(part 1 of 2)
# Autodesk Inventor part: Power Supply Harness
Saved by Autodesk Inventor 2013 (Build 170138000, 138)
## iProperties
Created: 2007-02
Part Number: Power Supply Harness
Document SubType Name: Modeling
Designer: floress
Density: 1 g/cm^3
Material: Allgemein
GlobalPropertyList: <PropertyList/>
Key:2|1|1|0|4|0|0|0|23|0|0|0|Level:1: <CableProperty entityType="Connector" version="1.0"><ID editable="" value=""/><UserDefined><Property name="14121" value="0.125 in" unitCategory="14110" custom="
Key:2|1|1|0|4|0|0|0|54|0|0|0|Level:1: <CableProperty entityType="Connector" version="1.0"><ID editable="" value=""/><UserDefined><Property name="14121" value="0.125 in" unitCategory="14110" custom="
Key:2|1|1|0|4|0|0|0|20|0|0|0|Level:1: <CableProperty entityType="Connector" version="1.0"><ID editable="" value=""/><UserDefined><Property name="14121" value="0.125 in" unitCategory="14110" custom="
Key:2|1|1|0|4|0|0|0|19|0|0|0|Level:1: <CableProperty entityType="Connector" version="1.0"><ID editable="" value=""/><UserDefined><Property name="14121" value="0.125 in" unitCategory="14110" custom="
Key:2|1|1|0|4|0|0|0|18|0|0|0|Level:1: <CableProperty entityType="Connector" version="1.0"><ID editable="" value=""/><UserDefined><Property name="14121" value="0.125 in" unitCategory="14110" custom="
Key:2|1|1|0|4|0|0|0|21|0|0|0|Level:1: <CableProperty entityType="Connector" version="1.0"><ID editable="" value=""/><UserDefined><Property name="14121" value="0.125 in" unitCategory="14110" custom="
Key:2|1|1|0|4|0|0|0|22|0|0|0|Level:1: <CableProperty entityType="Connector" version="1.0"><ID editable="" value=""/><UserDefined><Property name="14121" value="0.125 in" unitCategory="14110" custom="
Key:2|1|1|0|4|0|0|0|24|0|0|0|Level:1: <CableProperty entityType="Connector" version="1.0"><ID editable="" value=""/><UserDefined><Property name="14121" value="0.125 in" unitCategory="14110" custom="
Key:2|1|1|0|4|0|0|0|25|0|0|0|Level:1: <CableProperty entityType="Connector" version="1.0"><ID editable="" value=""/><UserDefined><Property name="14121" value="0.125 in" unitCategory="14110" custom="
Key:2|1|1|0|4|0|0|0|26|0|0|0|Level:1: <CableProperty entityType="Connector" version="1.0"><ID editable="" value=""/><UserDefined><Property name="14121" value="0.125 in" unitCategory="14110" custom="
Key:2|1|1|0|4|0|0|0|27|0|0|0|Level:1: <CableProperty entityType="Connector" version="1.0"><ID editable="" value=""/><UserDefined><Property name="14121" value="0.125 in" unitCategory="14110" custom="
Key:2|1|1|0|4|0|0|0|28|0|0|0|Level:1: <CableProperty entityType="Connector" version="1.0"><ID editable="" value=""/><UserDefined><Property name="14121" value="0.125 in" unitCategory="14110" custom="
Key:2|1|1|0|4|0|0|0|29|0|0|0|Level:1: <CableProperty entityType="Connector" version="1.0"><ID editable="" value=""/><UserDefined><Property name="14121" value="0.125 in" unitCategory="14110" custom="
Key:2|1|1|0|4|0|0|0|30|0|0|0|Level:1: <CableProperty entityType="Connector" version="1.0"><ID editable="" value=""/><UserDefined><Property name="14121" value="0.125 in" unitCategory="14110" custom="
Key:2|1|1|0|4|0|0|0|31|0|0|0|Level:1: <CableProperty entityType="Connector" version="1.0"><ID editable="" value=""/><UserDefined><Property name="14121" value="0.125 in" unitCategory="14110" custom="
Key:2|1|1|0|4|0|0|0|32|0|0|0|Level:1: <CableProperty entityType="Connector" version="1.0"><ID editable="" value=""/><UserDefined><Property name="14121" value="0.125 in" unitCategory="14110" custom="
Key:2|1|1|0|4|0|0|0|33|0|0|0|Level:1: <CableProperty entityType="Connector" version="1.0"><ID editable="" value=""/><UserDefined><Property name="14121" value="0.125 in" unitCategory="14110" custom="
Key:2|1|1|0|4|0|0|0|34|0|0|0|Level:1: <CableProperty entityType="Connector" version="1.0"><ID editable="" value=""/><UserDefined><Property name="14121" value="0.125 in" unitCategory="14110" custom="
Key:2|1|1|0|4|0|0|0|35|0|0|0|Level:1: <CableProperty entityType="Connector" version="1.0"><ID editable="" value=""/><UserDefined><Property name="14121" value="0.125 in" unitCategory="14110" custom="
Key:2|1|1|0|4|0|0|0|36|0|0|0|Level:1: <CableProperty entityType="Connector" version="1.0"><ID editable="" value=""/><UserDefined><Property name="14121" value="0.125 in" unitCategory="14110" custom="
Key:2|1|1|0|4|0|0|0|37|0|0|0|Level:1: <CableProperty entityType="Connector" version="1.0"><ID editable="" value=""/><UserDefined><Property name="14121" value="0.125 in" unitCategory="14110" custom="
Key:2|1|1|0|4|0|0|0|38|0|0|0|Level:1: <CableProperty entityType="Connector" version="1.0"><ID editable="" value=""/><UserDefined><Property name="14121" value="0.125 in" unitCategory="14110" custom="
Key:2|1|1|0|4|0|0|0|39|0|0|0|Level:1: <CableProperty entityType="Connector" version="1.0"><ID editable="" value=""/><UserDefined><Property name="14121" value="0.125 in" unitCategory="14110" custom="
Key:2|1|1|0|4|0|0|0|40|0|0|0|Level:1: <CableProperty entityType="Connector" version="1.0"><ID editable="" value=""/><UserDefined><Property name="14121" value="0.125 in" unitCategory="14110" custom="
Key:2|1|1|0|4|0|0|0|41|0|0|0|Level:1: <CableProperty entityType="Connector" version="1.0"><ID editable="" value=""/><UserDefined><Property name="14121" value="0.125 in" unitCategory="14110" custom="
Key:2|1|1|0|4|0|0|0|42|0|0|0|Level:1: <CableProperty entityType="Connector" version="1.0"><ID editable="" value=""/><UserDefined><Property name="14121" value="0.125 in" unitCategory="14110" custom="
Key:2|1|1|0|4|0|0|0|43|0|0|0|Level:1: <CableProperty entityType="Connector" version="1.0"><ID editable="" value=""/><UserDefined><Property name="14121" value="0.125 in" unitCategory="14110" custom="
Key:2|1|1|0|4|0|0|0|44|0|0|0|Level:1: <CableProperty entityType="Connector" version="1.0"><ID editable="" value=""/><UserDefined><Property name="14121" value="0.125 in" unitCategory="14110" custom="
Key:2|1|1|0|4|0|0|0|45|0|0|0|Level:1: <CableProperty entityType="Connector" version="1.0"><ID editable="" value=""/><UserDefined><Property name="14121" value="0.125 in" unitCategory="14110" custom="
Key:2|1|1|0|4|0|0|0|46|0|0|0|Level:1: <CableProperty entityType="Connector" version="1.0"><ID editable="" value=""/><UserDefined><Property name="14121" value="0.125 in" unitCategory="14110" custom="
Key:2|1|1|0|4|0|0|0|47|0|0|0|Level:1: <CableProperty entityType="Connector" version="1.0"><ID editable="" value=""/><UserDefined><Property name="14121" value="0.125 in" unitCategory="14110" custom="
Key:2|1|1|0|4|0|0|0|48|0|0|0|Level:1: <CableProperty entityType="Connector" version="1.0"><ID editable="" value=""/><UserDefined><Property name="14121" value="0.125 in" unitCategory="14110" custom="
Key:2|1|1|0|4|0|0|0|49|0|0|0|Level:1: <CableProperty entityType="Connector" version="1.0"><ID editable="" value=""/><UserDefined><Property name="14121" value="0.125 in" unitCategory="14110" custom="
Key:2|1|1|0|4|0|0|0|50|0|0|0|Level:1: <CableProperty entityType="Connector" version="1.0"><ID editable="" value=""/><UserDefined><Property name="14121" value="0.125 in" unitCategory="14110" custom="
Key:2|1|1|0|4|0|0|0|51|0|0|0|Level:1: <CableProperty entityType="Connector" version="1.0"><ID editable="" value=""/><UserDefined><Property name="14121" value="0.125 in" unitCategory="14110" custom="
Key:2|1|1|0|4|0|0|0|52|0|0|0|Level:1: <CableProperty entityType="Connector" version="1.0"><ID editable="" value=""/><UserDefined><Property name="14121" value="0.125 in" unitCategory="14110" custom="
Key:2|1|1|0|4|0|0|0|53|0|0|0|Level:1: <CableProperty entityType="Connector" version="1.0"><ID editable="" value=""/><UserDefined><Property name="14121" value="0.125 in" unitCategory="14110" custom="
Key:2|1|1|0|4|0|0|0|55|0|0|0|Level:1: <CableProperty entityType="Connector" version="1.0"><ID editable="" value=""/><UserDefined><Property name="14121" value="0.125 in" unitCategory="14110" custom="
Key:2|1|1|0|4|0|0|0|56|0|0|0|Level:1: <CableProperty entityType="Connector" version="1.0"><ID editable="" value=""/><UserDefined><Property name="14121" value="0.125 in" unitCategory="14110" custom="
Key:2|1|2|0|36|0|0|0|2|1|1|0|4|0|0|0|23|0|0|0|16|2|0|0|16|0|: <CableProperty entityType="ConnectorPin" version="1.0"><ID editable="" value=""/><UserDefined/><PinName editable="True" value="1"/><AttachedParts><AttachedPart 
Key:2|1|2|0|36|0|0|0|2|1|1|0|4|0|0|0|23|0|0|0|16|2|0|0|16|0|: <CableProperty entityType="ConnectorPin" version="1.0"><ID editable="" value=""/><UserDefined/><PinName editable="True" value="2"/><AttachedParts><AttachedPart 
Key:2|1|2|0|36|0|0|0|2|1|1|0|4|0|0|0|23|0|0|0|16|2|0|0|16|0|: <CableProperty entityType="ConnectorPin" version="1.0"><ID editable="" value=""/><UserDefined/><PinName editable="True" value="3"/><AttachedParts><AttachedPart 
Key:2|1|2|0|36|0|0|0|2|1|1|0|4|0|0|0|23|0|0|0|16|2|0|0|16|0|: <CableProperty entityType="ConnectorPin" version="1.0"><ID editable="" value=""/><UserDefined/><PinName editable="True" value="4"/><AttachedParts><AttachedPart 
Key:2|1|2|0|36|0|0|0|2|1|1|0|4|0|0|0|23|0|0|0|16|2|0|0|16|0|: <CableProperty entityType="ConnectorPin" version="1.0"><ID editable="" value=""/><UserDefined/><PinName editable="True" value="5"/><AttachedParts><AttachedPart 
Key:2|1|2|0|36|0|0|0|2|1|1|0|4|0|0|0|23|0|0|0|16|2|0|0|16|0|: <CableProperty entityType="ConnectorPin" version="1.0"><ID editable="" value=""/><UserDefined/><PinName editable="True" value="6"/><AttachedParts><AttachedPart 
Key:2|1|2|0|36|0|0|0|2|1|1|0|4|0|0|0|23|0|0|0|16|2|0|0|16|0|: <CableProperty entityType="ConnectorPin" version="1.0"><ID editable="" value=""/><UserDefined/><PinName editable="True" value="7"/><AttachedParts><AttachedPart 
Key:2|1|2|0|36|0|0|0|2|1|1|0|4|0|0|0|23|0|0|0|16|2|0|0|16|0|: <CableProperty entityType="ConnectorPin" version="1.0"><ID editable="" value=""/><UserDefined/><PinName editable="True" value="8"/><AttachedParts><AttachedPart 
Key:2|1|2|0|36|0|0|0|2|1|1|0|4|0|0|0|23|0|0|0|16|2|0|0|16|0|: <CableProperty entityType="ConnectorPin" version="1.0"><ID editable="" value=""/><UserDefined/><PinName editable="True" value="9"/><AttachedParts><AttachedPart 
Key:2|1|2|0|36|0|0|0|2|1|1|0|4|0|0|0|23|0|0|0|16|2|0|0|16|0|: <CableProperty entityType="ConnectorPin" version="1.0"><ID editable="" value=""/><UserDefined/><PinName editable="True" value="10"/><AttachedParts><AttachedPart
Key:2|1|2|0|36|0|0|0|2|1|1|0|4|0|0|0|23|0|0|0|16|2|0|0|16|0|: <CableProperty entityType="ConnectorPin" version="1.0"><ID editable="" value=""/><UserDefined/><PinName editable="True" value="11"/><AttachedParts><AttachedPart
Key:2|1|2|0|36|0|0|0|2|1|1|0|4|0|0|0|23|0|0|0|16|2|0|0|16|0|: <CableProperty entityType="ConnectorPin" version="1.0"><ID editable="" value=""/><UserDefined/><PinName editable="True" value="12"/><AttachedParts><AttachedPart
Key:2|1|2|0|36|0|0|0|2|1|1|0|4|0|0|0|23|0|0|0|16|2|0|0|16|0|: <CableProperty entityType="ConnectorPin" version="1.0"><ID editable="" value=""/><UserDefined/><PinName editable="True" value="13"/><AttachedParts><AttachedPart
Key:2|1|2|0|36|0|0|0|2|1|1|0|4|0|0|0|23|0|0|0|16|2|0|0|16|0|: <CableProperty entityType="ConnectorPin" version="1.0"><ID editable="" value=""/><UserDefined/><PinName editable="True" value="14"/><AttachedParts><AttachedPart
Key:2|1|2|0|36|0|0|0|2|1|1|0|4|0|0|0|23|0|0|0|16|2|0|0|16|0|: <CableProperty entityType="ConnectorPin" version="1.0"><ID editable="" value=""/><UserDefined/><PinName editable="True" value="15"/><AttachedParts><AttachedPart
Key:2|1|2|0|36|0|0|0|2|1|1|0|4|0|0|0|23|0|0|0|16|2|0|0|16|0|: <CableProperty entityType="ConnectorPin" version="1.0"><ID editable="" value=""/><UserDefined/><PinName editable="True" value="16"/><AttachedParts><AttachedPart
Key:2|1|2|0|36|0|0|0|2|1|1|0|4|0|0|0|23|0|0|0|16|2|0|0|16|0|: <CableProperty entityType="ConnectorPin" version="1.0"><ID editable="" value=""/><UserDefined/><PinName editable="True" value="17"/><AttachedParts><AttachedPart
Key:2|1|2|0|36|0|0|0|2|1|1|0|4|0|0|0|23|0|0|0|16|2|0|0|16|0|: <CableProperty entityType="ConnectorPin" version="1.0"><ID editable="" value=""/><UserDefined/><PinName editable="True" value="18"/><AttachedParts><AttachedPart
Key:2|1|2|0|36|0|0|0|2|1|1|0|4|0|0|0|23|0|0|0|16|2|0|0|16|0|: <CableProperty entityType="ConnectorPin" version="1.0"><ID editable="" value=""/><UserDefined/><PinName editable="True" value="19"/><AttachedParts><AttachedPart
Key:2|1|2|0|36|0|0|0|2|1|1|0|4|0|0|0|23|0|0|0|16|2|0|0|16|0|: <CableProperty entityType="ConnectorPin" version="1.0"><ID editable="" value=""/><UserDefined/><PinName editable="True" value="20"/><AttachedParts><AttachedPart
Key:2|1|2|0|36|0|0|0|2|1|1|0|4|0|0|0|19|0|0|0|16|2|0|0|16|0|: <CableProperty entityType="ConnectorPin" version="1.0"><ID editable="" value=""/><UserDefined/><PinName editable="True" value="1"/><AttachedParts><AttachedPart 
Key:2|1|2|0|36|0|0|0|2|1|1|0|4|0|0|0|19|0|0|0|16|2|0|0|16|0|: <CableProperty entityType="ConnectorPin" version="1.0"><ID editable="" value=""/><UserDefined/><PinName editable="True" value="2"/><AttachedParts><AttachedPart 
Key:2|1|2|0|36|0|0|0|2|1|1|0|4|0|0|0|19|0|0|0|16|2|0|0|16|0|: <CableProperty entityType="ConnectorPin" version="1.0"><ID editable="" value=""/><UserDefined/><PinName editable="True" value="3"/><AttachedParts><AttachedPart 
Key:2|1|2|0|36|0|0|0|2|1|1|0|4|0|0|0|19|0|0|0|16|2|0|0|16|0|: <CableProperty entityType="ConnectorPin" version="1.0"><ID editable="" value=""/><UserDefined/><PinName editable="True" value="4"/><AttachedParts><AttachedPart 
Key:2|1|2|0|36|0|0|0|2|1|1|0|4|0|0|0|20|0|0|0|16|2|0|0|16|0|: <CableProperty entityType="ConnectorPin" version="1.0"><ID editable="" value=""/><UserDefined/><PinName editable="True" value="1"/><AttachedParts><AttachedPart 
Key:2|1|2|0|36|0|0|0|2|1|1|0|4|0|0|0|20|0|0|0|16|2|0|0|16|0|: <CableProperty entityType="ConnectorPin" version="1.0"><ID editable="" value=""/><UserDefined/><PinName editable="True" value="2"/><AttachedParts><AttachedPart 
Key:2|1|2|0|36|0|0|0|2|1|1|0|4|0|0|0|20|0|0|0|16|2|0|0|16|0|: <CableProperty entityType="ConnectorPin" version="1.0"><ID editable="" value=""/><UserDefined/><PinName editable="True" value="3"/><AttachedParts><AttachedPart 
Key:2|1|2|0|36|0|0|0|2|1|1|0|4|0|0|0|20|0|0|0|16|2|0|0|16|0|: <CableProperty entityType="ConnectorPin" version="1.0"><ID editable="" value=""/><UserDefined/><PinName editable="True" value="4"/><AttachedParts><AttachedPart 
Key:2|1|2|0|36|0|0|0|2|1|1|0|4|0|0|0|54|0|0|0|16|2|0|0|16|0|: <CableProperty entityType="ConnectorPin" version="1.0"><ID editable="" value=""/><UserDefined/><PinName editable="True" value="1"/><AttachedParts><AttachedPart 
Key:2|1|2|0|36|0|0|0|2|1|1|0|4|0|0|0|54|0|0|0|16|2|0|0|16|0|: <CableProperty entityType="ConnectorPin" version="1.0"><ID editable="" value=""/><UserDefined/><PinName editable="True" value="2"/><AttachedParts><AttachedPart 
Key:2|1|2|0|36|0|0|0|2|1|1|0|4|0|0|0|54|0|0|0|16|2|0|0|16|0|: <CableProperty entityType="ConnectorPin" version="1.0"><ID editable="" value=""/><UserDefined/><PinName editable="True" value="3"/><AttachedParts><AttachedPart 
Key:2|1|2|0|36|0|0|0|2|1|1|0|4|0|0|0|54|0|0|0|16|2|0|0|16|0|: <CableProperty entityType="ConnectorPin" version="1.0"><ID editable="" value=""/><UserDefined/><PinName editable="True" value="4"/><AttachedParts><AttachedPart 
Key:2|1|2|0|36|0|0|0|2|1|1|0|4|0|0|0|18|0|0|0|16|2|0|0|16|0|: <CableProperty entityType="ConnectorPin" version="1.0"><ID editable="" value=""/><UserDefined/><PinName editable="True" value="1"/><AttachedParts><AttachedPart 
Key:2|1|2|0|36|0|0|0|2|1|1|0|4|0|0|0|18|0|0|0|16|2|0|0|16|0|: <CableProperty entityType="ConnectorPin" version="1.0"><ID editable="" value=""/><UserDefined/><PinName editable="True" value="2"/><AttachedParts><AttachedPart 
Key:2|1|2|0|36|0|0|0|2|1|1|0|4|0|0|0|18|0|0|0|16|2|0|0|16|0|: <CableProperty entityType="ConnectorPin" version="1.0"><ID editable="" value=""/><UserDefined/><PinName editable="True" value="3"/><AttachedParts><AttachedPart 
Key:2|1|2|0|36|0|0|0|2|1|1|0|4|0|0|0|18|0|0|0|16|2|0|0|16|0|: <CableProperty entityType="ConnectorPin" version="1.0"><ID editable="" value=""/><UserDefined/><PinName editable="True" value="4"/><AttachedParts><AttachedPart 
Key:2|1|2|0|36|0|0|0|2|1|1|0|4|0|0|0|21|0|0|0|16|2|0|0|16|0|: <CableProperty entityType="ConnectorPin" version="1.0"><ID editable="" value=""/><UserDefined/><PinName editable="True" value="1"/><AttachedParts><AttachedPart 
Key:2|1|2|0|36|0|0|0|2|1|1|0|4|0|0|0|21|0|0|0|16|2|0|0|16|0|: <CableProperty entityType="ConnectorPin" version="1.0"><ID editable="" value=""/><UserDefined/><PinName editable="True" value="2"/><AttachedParts><AttachedPart 
Key:2|1|2|0|36|0|0|0|2|1|1|0|4|0|0|0|21|0|0|0|16|2|0|0|16|0|: <CableProperty entityType="ConnectorPin" version="1.0"><ID editable="" value=""/><UserDefined/><PinName editable="True" value="3"/><AttachedParts><AttachedPart 
Key:2|1|2|0|36|0|0|0|2|1|1|0|4|0|0|0|21|0|0|0|16|2|0|0|16|0|: <CableProperty entityType="ConnectorPin" version="1.0"><ID editable="" value=""/><UserDefined/><PinName editable="True" value="4"/><AttachedParts><AttachedPart 
Key:2|1|2|0|36|0|0|0|2|1|1|0|4|0|0|0|22|0|0|0|16|2|0|0|16|0|: <CableProperty entityType="ConnectorPin" version="1.0"><ID editable="" value=""/><UserDefined/><PinName editable="True" value="1"/><AttachedParts><AttachedPart 
Key:2|1|2|0|36|0|0|0|2|1|1|0|4|0|0|0|22|0|0|0|16|2|0|0|16|0|: <CableProperty entityType="ConnectorPin" version="1.0"><ID editable="" value=""/><UserDefined/><PinName editable="True" value="2"/><AttachedParts><AttachedPart 
Key:2|1|2|0|36|0|0|0|2|1|1|0|4|0|0|0|22|0|0|0|16|2|0|0|16|0|: <CableProperty entityType="ConnectorPin" version="1.0"><ID editable="" value=""/><UserDefined/><PinName editable="True" value="3"/><AttachedParts><AttachedPart 
Key:2|1|2|0|36|0|0|0|2|1|1|0|4|0|0|0|22|0|0|0|16|2|0|0|16|0|: <CableProperty entityType="ConnectorPin" version="1.0"><ID editable="" value=""/><UserDefined/><PinName editable="True" value="4"/><AttachedParts><AttachedPart 
Key:2|1|1|0|4|0|0|0|166|0|0|0|Level:1: <CableProperty entityType="Connector" version="1.0"><ID editable="" value=""/><UserDefined><Property name="14121" value="0.125 in" unitCategory="14110" custom="
Key:2|1|1|0|4|0|0|0|167|0|0|0|Level:1: <CableProperty entityType="Connector" version="1.0"><ID editable="" value=""/><UserDefined><Property name="14121" value="0.125 in" unitCategory="14110" custom="
Key:2|1|1|0|4|0|0|0|168|0|0|0|Level:1: <CableProperty entityType="Connector" version="1.0"><ID editable="" value=""/><UserDefined><Property name="14121" value="0.125 in" unitCategory="14110" custom="
Key:2|1|1|0|4|0|0|0|169|0|0|0|Level:1: <CableProperty entityType="Connector" version="1.0"><ID editable="" value=""/><UserDefined><Property name="14121" value="0.125 in" unitCategory="14110" custom="
Key:2|1|1|0|4|0|0|0|170|0|0|0|Level:1: <CableProperty entityType="Connector" version="1.0"><ID editable="" value=""/><UserDefined><Property name="14121" value="0.125 in" unitCategory="14110" custom="
Key:2|1|1|0|4|0|0|0|171|0|0|0|Level:1: <CableProperty entityType="Connector" version="1.0"><ID editable="" value=""/><UserDefined><Property name="14121" value="0.125 in" unitCategory="14110" custom="
Key:2|1|1|0|4|0|0|0|172|0|0|0|Level:1: <CableProperty entityType="Connector" version="1.0"><ID editable="" value=""/><UserDefined><Property name="14121" value="0.125 in" unitCategory="14110" custom="
Key:2|1|1|0|4|0|0|0|173|0|0|0|Level:1: <CableProperty entityType="Connector" version="1.0"><ID editable="" value=""/><UserDefined><Property name="14121" value="0.125 in" unitCategory="14110" custom="
Key:2|1|1|0|4|0|0|0|174|0|0|0|Level:1: <CableProperty entityType="Connector" version="1.0"><ID editable="" value=""/><UserDefined><Property name="14121" value="0.125 in" unitCategory="14110" custom="
Key:2|1|1|0|4|0|0|0|175|0|0|0|Level:1: <CableProperty entityType="Connector" version="1.0"><ID editable="" value=""/><UserDefined><Property name="14121" value="0.125 in" unitCategory="14110" custom="
Key:2|1|1|0|4|0|0|0|176|0|0|0|Level:1: <CableProperty entityType="Connector" version="1.0"><ID editable="" value=""/><UserDefined><Property name="14121" value="0.125 in" unitCategory="14110" custom="
Key:2|1|1|0|4|0|0|0|177|0|0|0|Level:1: <CableProperty entityType="Connector" version="1.0"><ID editable="" value=""/><UserDefined><Property name="14121" value="0.125 in" unitCategory="14110" custom="
Key:2|1|1|0|4|0|0|0|178|0|0|0|Level:1: <CableProperty entityType="Connector" version="1.0"><ID editable="" value=""/><UserDefined><Property name="14121" value="0.125 in" unitCategory="14110" custom="
Key:2|1|1|0|4|0|0|0|179|0|0|0|Level:1: <CableProperty entityType="Connector" version="1.0"><ID editable="" value=""/><UserDefined><Property name="14121" value="0.125 in" unitCategory="14110" custom="
Key:2|1|1|0|4|0|0|0|180|0|0|0|Level:1: <CableProperty entityType="Connector" version="1.0"><ID editable="" value=""/><UserDefined><Property name="14121" value="0.125 in" unitCategory="14110" custom="
Key:2|1|1|0|4|0|0|0|181|0|0|0|Level:1: <CableProperty entityType="Connector" version="1.0"><ID editable="" value=""/><UserDefined><Property name="14121" value="0.125 in" unitCategory="14110" custom="
Key:2|1|1|0|4|0|0|0|182|0|0|0|Level:1: <CableProperty entityType="Connector" version="1.0"><ID editable="" value=""/><UserDefined><Property name="14121" value="0.125 in" unitCategory="14110" custom="
Key:2|1|1|0|4|0|0|0|183|0|0|0|Level:1: <CableProperty entityType="Connector" version="1.0"><ID editable="" value=""/><UserDefined><Property name="14121" value="0.125 in" unitCategory="14110" custom="
Key:2|1|1|0|4|0|0|0|184|0|0|0|Level:1: <CableProperty entityType="Connector" version="1.0"><ID editable="" value=""/><UserDefined><Property name="14121" value="0.125 in" unitCategory="14110" custom="
Key:2|1|1|0|4|0|0|0|185|0|0|0|Level:1: <CableProperty entityType="Connector" version="1.0"><ID editable="" value=""/><UserDefined><Property name="14121" value="0.125 in" unitCategory="14110" custom="
Key:2|1|1|0|4|0|0|0|186|0|0|0|Level:1: <CableProperty entityType="Connector" version="1.0"><ID editable="" value=""/><UserDefined><Property name="14121" value="0.125 in" unitCategory="14110" custom="
Key:2|1|1|0|4|0|0|0|187|0|0|0|Level:1: <CableProperty entityType="Connector" version="1.0"><ID editable="" value=""/><UserDefined><Property name="14121" value="0.125 in" unitCategory="14110" custom="
Key:2|1|1|0|4|0|0|0|158|0|0|0|Level:1: <CableProperty entityType="Connector" version="1.0"><ID editable="" value=""/><UserDefined><Property name="14121" value="0.125 in" unitCategory="14110" custom="
Key:2|1|1|0|4|0|0|0|159|0|0|0|Level:1: <CableProperty entityType="Connector" version="1.0"><ID editable="" value=""/><UserDefined><Property name="14121" value="0.125 in" unitCategory="14110" custom="
Key:2|1|1|0|4|0|0|0|160|0|0|0|Level:1: <CableProperty entityType="Connector" version="1.0"><ID editable="" value=""/><UserDefined><Property name="14121" value="0.125 in" unitCategory="14110" custom="
Key:2|1|1|0|4|0|0|0|161|0|0|0|Level:1: <CableProperty entityType="Connector" version="1.0"><ID editable="" value=""/><UserDefined><Property name="14121" value="0.125 in" unitCategory="14110" custom="
Key:2|1|1|0|4|0|0|0|162|0|0|0|Level:1: <CableProperty entityType="Connector" version="1.0"><ID editable="" value=""/><UserDefined><Property name="14121" value="0.125 in" unitCategory="14110" custom="
Key:2|1|1|0|4|0|0|0|163|0|0|0|Level:1: <CableProperty entityType="Connector" version="1.0"><ID editable="" value=""/><UserDefined><Property name="14121" value="0.125 in" unitCategory="14110" custom="
Key:2|1|1|0|4|0|0|0|164|0|0|0|Level:1: <CableProperty entityType="Connector" version="1.0"><ID editable="" value=""/><UserDefined><Property name="14121" value="0.125 in" unitCategory="14110" custom="
Key:2|1|1|0|4|0|0|0|165|0|0|0|Level:1: <CableProperty entityType="Connector" version="1.0"><ID editable="" value=""/><UserDefined><Property name="14121" value="0.125 in" unitCategory="14110" custom="
Key:2|1|1|0|4|0|0|0|157|0|0|0|Level:1: <CableProperty entityType="Connector" version="1.0"><ID editable="" value=""/><UserDefined><Property name="14121" value="0.125 in" unitCategory="14110" custom="
Key:2|1|1|0|4|0|0|0|153|0|0|0|Level:1: <CableProperty entityType="Connector" version="1.0"><ID editable="" value=""/><UserDefined><Property name="14121" value="0.125 in" unitCategory="14110" custom="
Key:2|1|1|0|4|0|0|0|154|0|0|0|Level:1: <CableProperty entityType="Connector" version="1.0"><ID editable="" value=""/><UserDefined><Property name="14121" value="0.125 in" unitCategory="14110" custom="
Key:2|1|1|0|4|0|0|0|188|0|0|0|Level:1: <CableProperty entityType="Connector" version="1.0"><ID editable="" value=""/><UserDefined><Property name="14121" value="0.125 in" unitCategory="14110" custom="
Key:2|1|1|0|4|0|0|0|152|0|0|0|Level:1: <CableProperty entityType="Connector" version="1.0"><ID editable="" value=""/><UserDefined><Property name="14121" value="0.125 in" unitCategory="14110" custom="
Key:2|1|1|0|4|0|0|0|155|0|0|0|Level:1: <CableProperty entityType="Connector" version="1.0"><ID editable="" value=""/><UserDefined><Property name="14121" value="0.125 in" unitCategory="14110" custom="
Key:2|1|1|0|4|0|0|0|156|0|0|0|Level:1: <CableProperty entityType="Connector" version="1.0"><ID editable="" value=""/><UserDefined><Property name="14121" value="0.125 in" unitCategory="14110" custom="
Key:2|1|1|0|4|0|0|0|189|0|0|0|Level:1: <CableProperty entityType="Connector" version="1.0"><ID editable="" value=""/><UserDefined><Property name="14121" value="0.125 in" unitCategory="14110" custom="
Key:2|1|1|0|4|0|0|0|190|0|0|0|Level:1: <CableProperty entityType="Connector" version="1.0"><ID editable="" value=""/><UserDefined><Property name="14121" value="0.125 in" unitCategory="14110" custom="
Key:2|1|2|0|36|0|0|0|2|1|1|0|4|0|0|0|157|0|0|0|16|2|0|0|16|0: <CableProperty entityType="ConnectorPin" version="1.0"><ID editable="" value=""/><UserDefined/><PinName editable="True" value="1"/><AttachedParts><AttachedPart 
Key:2|1|2|0|36|0|0|0|2|1|1|0|4|0|0|0|157|0|0|0|16|2|0|0|16|0: <CableProperty entityType="ConnectorPin" version="1.0"><ID editable="" value=""/><UserDefined/><PinName editable="True" value="2"/><AttachedParts><AttachedPart 
Key:2|1|2|0|36|0|0|0|2|1|1|0|4|0|0|0|157|0|0|0|16|2|0|0|16|0: <CableProperty entityType="ConnectorPin" version="1.0"><ID editable="" value=""/><UserDefined/><PinName editable="True" value="3"/><AttachedParts><AttachedPart 
Key:2|1|2|0|36|0|0|0|2|1|1|0|4|0|0|0|157|0|0|0|16|2|0|0|16|0: <CableProperty entityType="ConnectorPin" version="1.0"><ID editable="" value=""/><UserDefined/><PinName editable="True" value="4"/><AttachedParts><AttachedPart 
Key:2|1|2|0|36|0|0|0|2|1|1|0|4|0|0|0|157|0|0|0|16|2|0|0|16|0: <CableProperty entityType="ConnectorPin" version="1.0"><ID editable="" value=""/><UserDefined/><PinName editable="True" value="5"/><AttachedParts><AttachedPart 
Key:2|1|2|0|36|0|0|0|2|1|1|0|4|0|0|0|157|0|0|0|16|2|0|0|16|0: <CableProperty entityType="ConnectorPin" version="1.0"><ID editable="" value=""/><UserDefined/><PinName editable="True" value="6"/><AttachedParts><AttachedPart 
Key:2|1|2|0|36|0|0|0|2|1|1|0|4|0|0|0|157|0|0|0|16|2|0|0|16|0: <CableProperty entityType="ConnectorPin" version="1.0"><ID editable="" value=""/><UserDefined/><PinName editable="True" value="7"/><AttachedParts><AttachedPart 
Key:2|1|2|0|36|0|0|0|2|1|1|0|4|0|0|0|157|0|0|0|16|2|0|0|16|0: <CableProperty entityType="ConnectorPin" version="1.0"><ID editable="" value=""/><UserDefined/><PinName editable="True" value="8"/><AttachedParts><AttachedPart 
Key:2|1|2|0|36|0|0|0|2|1|1|0|4|0|0|0|157|0|0|0|16|2|0|0|16|0: <CableProperty entityType="ConnectorPin" version="1.0"><ID editable="" value=""/><UserDefined/><PinName editable="True" value="9"/><AttachedParts><AttachedPart 
Key:2|1|2|0|36|0|0|0|2|1|1|0|4|0|0|0|157|0|0|0|16|2|0|0|16|0: <CableProperty entityType="ConnectorPin" version="1.0"><ID editable="" value=""/><UserDefined/><PinName editable="True" value="10"/><AttachedParts><AttachedPart
Key:2|1|2|0|36|0|0|0|2|1|1|0|4|0|0|0|157|0|0|0|16|2|0|0|16|0: <CableProperty entityType="ConnectorPin" version="1.0"><ID editable="" value=""/><UserDefined/><PinName editable="True" value="11"/><AttachedParts><AttachedPart
Key:2|1|2|0|36|0|0|0|2|1|1|0|4|0|0|0|157|0|0|0|16|2|0|0|16|0: <CableProperty entityType="ConnectorPin" version="1.0"><ID editable="" value=""/><UserDefined/><PinName editable="True" value="12"/><AttachedParts><AttachedPart
Key:2|1|2|0|36|0|0|0|2|1|1|0|4|0|0|0|157|0|0|0|16|2|0|0|16|0: <CableProperty entityType="ConnectorPin" version="1.0"><ID editable="" value=""/><UserDefined/><PinName editable="True" value="13"/><AttachedParts><AttachedPart
Key:2|1|2|0|36|0|0|0|2|1|1|0|4|0|0|0|157|0|0|0|16|2|0|0|16|0: <CableProperty entityType="ConnectorPin" version="1.0"><ID editable="" value=""/><UserDefined/><PinName editable="True" value="14"/><AttachedParts><AttachedPart
Key:2|1|2|0|36|0|0|0|2|1|1|0|4|0|0|0|157|0|0|0|16|2|0|0|16|0: <CableProperty entityType="ConnectorPin" version="1.0"><ID editable="" value=""/><UserDefined/><PinName editable="True" value="15"/><AttachedParts><AttachedPart
Key:2|1|2|0|36|0|0|0|2|1|1|0|4|0|0|0|157|0|0|0|16|2|0|0|16|0: <CableProperty entityType="ConnectorPin" version="1.0"><ID editable="" value=""/><UserDefined/><PinName editable="True" value="16"/><AttachedParts><AttachedPart
Key:2|1|2|0|36|0|0|0|2|1|1|0|4|0|0|0|157|0|0|0|16|2|0|0|16|0: <CableProperty entityType="ConnectorPin" version="1.0"><ID editable="" value=""/><UserDefined/><PinName editable="True" value="17"/><AttachedParts><AttachedPart
Key:2|1|2|0|36|0|0|0|2|1|1|0|4|0|0|0|157|0|0|0|16|2|0|0|16|0: <CableProperty entityType="ConnectorPin" version="1.0"><ID editable="" value=""/><UserDefined/><PinName editable="True" value="18"/><AttachedParts><AttachedPart
Key:2|1|2|0|36|0|0|0|2|1|1|0|4|0|0|0|157|0|0|0|16|2|0|0|16|0: <CableProperty entityType="ConnectorPin" version="1.0"><ID editable="" value=""/><UserDefined/><PinName editable="True" value="19"/><AttachedParts><AttachedPart
Key:2|1|2|0|36|0|0|0|2|1|1|0|4|0|0|0|157|0|0|0|16|2|0|0|16|0: <CableProperty entityType="ConnectorPin" version="1.0"><ID editable="" value=""/><UserDefined/><PinName editable="True" value="20"/><AttachedParts><AttachedPart
Key:2|1|2|0|36|0|0|0|2|1|1|0|4|0|0|0|153|0|0|0|16|2|0|0|16|0: <CableProperty entityType="ConnectorPin" version="1.0"><ID editable="" value=""/><UserDefined/><PinName editable="True" value="1"/><AttachedParts><AttachedPart 
Key:2|1|2|0|36|0|0|0|2|1|1|0|4|0|0|0|153|0|0|0|16|2|0|0|16|0: <CableProperty entityType="ConnectorPin" version="1.0"><ID editable="" value=""/><UserDefined/><PinName editable="True" value="2"/><AttachedParts><AttachedPart 
Key:2|1|2|0|36|0|0|0|2|1|1|0|4|0|0|0|153|0|0|0|16|2|0|0|16|0: <CableProperty entityType="ConnectorPin" version="1.0"><ID editable="" value=""/><UserDefined/><PinName editable="True" value="3"/><AttachedParts><AttachedPart 
Key:2|1|2|0|36|0|0|0|2|1|1|0|4|0|0|0|153|0|0|0|16|2|0|0|16|0: <CableProperty entityType="ConnectorPin" version="1.0"><ID editable="" value=""/><UserDefined/><PinName editable="True" value="4"/><AttachedParts><AttachedPart 
Key:2|1|2|0|36|0|0|0|2|1|1|0|4|0|0|0|154|0|0|0|16|2|0|0|16|0: <CableProperty entityType="ConnectorPin" version="1.0"><ID editable="" value=""/><UserDefined/><PinName editable="True" value="1"/><AttachedParts><AttachedPart 
Key:2|1|2|0|36|0|0|0|2|1|1|0|4|0|0|0|154|0|0|0|16|2|0|0|16|0: <CableProperty entityType="ConnectorPin" version="1.0"><ID editable="" value=""/><UserDefined/><PinName editable="True" value="2"/><AttachedParts><AttachedPart 
Key:2|1|2|0|36|0|0|0|2|1|1|0|4|0|0|0|154|0|0|0|16|2|0|0|16|0: <CableProperty entityType="ConnectorPin" version="1.0"><ID editable="" value=""/><UserDefined/><PinName editable="True" value="3"/><AttachedParts><AttachedPart 
Key:2|1|2|0|36|0|0|0|2|1|1|0|4|0|0|0|154|0|0|0|16|2|0|0|16|0: <CableProperty entityType="ConnectorPin" version="1.0"><ID editable="" value=""/><UserDefined/><PinName editable="True" value="4"/><AttachedParts><AttachedPart 
Key:2|1|2|0|36|0|0|0|2|1|1|0|4|0|0|0|188|0|0|0|16|2|0|0|16|0: <CableProperty entityType="ConnectorPin" version="1.0"><ID editable="" value=""/><UserDefined/><PinName editable="True" value="1"/><AttachedParts><AttachedPart 
Key:2|1|2|0|36|0|0|0|2|1|1|0|4|0|0|0|188|0|0|0|16|2|0|0|16|0: <CableProperty entityType="ConnectorPin" version="1.0"><ID editable="" value=""/><UserDefined/><PinName editable="True" value="2"/><AttachedParts><AttachedPart 
Key:2|1|2|0|36|0|0|0|2|1|1|0|4|0|0|0|188|0|0|0|16|2|0|0|16|0: <CableProperty entityType="ConnectorPin" version="1.0"><ID editable="" value=""/><UserDefined/><PinName editable="True" value="3"/><AttachedParts><AttachedPart 
Key:2|1|2|0|36|0|0|0|2|1|1|0|4|0|0|0|188|0|0|0|16|2|0|0|16|0: <CableProperty entityType="ConnectorPin" version="1.0"><ID editable="" value=""/><UserDefined/><PinName editable="True" value="4"/><AttachedParts><AttachedPart 
Key:2|1|2|0|36|0|0|0|2|1|1|0|4|0|0|0|152|0|0|0|16|2|0|0|16|0: <CableProperty entityType="ConnectorPin" version="1.0"><ID editable="" value=""/><UserDefined/><PinName editable="True" value="1"/><AttachedParts><AttachedPart 
Key:2|1|2|0|36|0|0|0|2|1|1|0|4|0|0|0|152|0|0|0|16|2|0|0|16|0: <CableProperty entityType="ConnectorPin" version="1.0"><ID editable="" value=""/><UserDefined/><PinName editable="True" value="2"/><AttachedParts><AttachedPart 
Key:2|1|2|0|36|0|0|0|2|1|1|0|4|0|0|0|152|0|0|0|16|2|0|0|16|0: <CableProperty entityType="ConnectorPin" version="1.0"><ID editable="" value=""/><UserDefined/><PinName editable="True" value="3"/><AttachedParts><AttachedPart 
Key:2|1|2|0|36|0|0|0|2|1|1|0|4|0|0|0|152|0|0|0|16|2|0|0|16|0: <CableProperty entityType="ConnectorPin" version="1.0"><ID editable="" value=""/><UserDefined/><PinName editable="True" value="4"/><AttachedParts><AttachedPart 
Key:2|1|2|0|36|0|0|0|2|1|1|0|4|0|0|0|155|0|0|0|16|2|0|0|16|0: <CableProperty entityType="ConnectorPin" version="1.0"><ID editable="" value=""/><UserDefined/><PinName editable="True" value="1"/><AttachedParts><AttachedPart 
Key:2|1|2|0|36|0|0|0|2|1|1|0|4|0|0|0|155|0|0|0|16|2|0|0|16|0: <CableProperty entityType="ConnectorPin" version="1.0"><ID editable="" value=""/><UserDefined/><PinName editable="True" value="2"/><AttachedParts><AttachedPart 
Key:2|1|2|0|36|0|0|0|2|1|1|0|4|0|0|0|155|0|0|0|16|2|0|0|16|0: <CableProperty entityType="ConnectorPin" version="1.0"><ID editable="" value=""/><UserDefined/><PinName editable="True" value="3"/><AttachedParts><AttachedPart 
Key:2|1|2|0|36|0|0|0|2|1|1|0|4|0|0|0|155|0|0|0|16|2|0|0|16|0: <CableProperty entityType="ConnectorPin" version="1.0"><ID editable="" value=""/><UserDefined/><PinName editable="True" value="4"/><AttachedParts><AttachedPart 
Key:2|1|2|0|36|0|0|0|2|1|1|0|4|0|0|0|156|0|0|0|16|2|0|0|16|0: <CableProperty entityType="ConnectorPin" version="1.0"><ID editable="" value=""/><UserDefined/><PinName editable="True" value="1"/><AttachedParts><AttachedPart 
Key:2|1|2|0|36|0|0|0|2|1|1|0|4|0|0|0|156|0|0|0|16|2|0|0|16|0: <CableProperty entityType="ConnectorPin" version="1.0"><ID editable="" value=""/><UserDefined/><PinName editable="True" value="2"/><AttachedParts><AttachedPart 
Key:2|1|2|0|36|0|0|0|2|1|1|0|4|0|0|0|156|0|0|0|16|2|0|0|16|0: <CableProperty entityType="ConnectorPin" version="1.0"><ID editable="" value=""/><UserDefined/><PinName editable="True" value="3"/><AttachedParts><AttachedPart 
Key:2|1|2|0|36|0|0|0|2|1|1|0|4|0|0|0|156|0|0|0|16|2|0|0|16|0: <CableProperty entityType="ConnectorPin" version="1.0"><ID editable="" value=""/><UserDefined/><PinName editable="True" value="4"/><AttachedParts><AttachedPart 
Author: floress
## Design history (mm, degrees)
workpoint "Work Point89"
workpoint "Work Point90"
sketch "Segment1"
workpoint "Work Point91"
workpoint "Work Point92"
workpoint "Work Point93"
workpoint "Work Point94"
workpoint "Work Point95"
workpoint "Work Point96"
workplane "Work Plane1"
sketch "Sketch1"
  geometry: C1 r 3.799 at (0, 0); 1 further point
  constraints: 1 centre point
feature "SweepSrf1" sketch "Sketch1" dims "d0" = 0
workpoint "Work Point97"
workpoint "Work Point98"
sketch "Segment2"
workpoint "Work Point99"
workpoint "Work Point100"
workpoint "Work Point101"
workpoint "Work Point102"
workpoint "Work Point103"
workpoint "Work Point104"
workpoint "Work Point105"
workpoint "Work Point106"
workplane "Work Plane2"
sketch "Sketch2"
  geometry: C1 r 1.388 at (0, 0); 1 further point
  constraints: 1 centre point
feature "SweepSrf2" sketch "Sketch2" dims "d1" = 0
workpoint "Work Point107"
workpoint "Work Point108"
sketch "Segment3"
workpoint "Work Point109"
workpoint "Work Point110"
workpoint "Work Point111"
workpoint "Work Point112"
workplane "Work Plane3"
sketch "Sketch3"
  geometry: C1 r 1.388 at (0, 0); 1 further point
  constraints: 1 centre point
feature "SweepSrf3" sketch "Sketch3" dims "d2" = 0
workpoint "Work Point113"
sketch "Segment4"
workpoint "Work Point114"
workpoint "Work Point115"
workpoint "Work Point116"
workplane "Work Plane4"
sketch "Sketch4"
  geometry: C1 r 1.388 at (0, 0); 1 further point
  constraints: 1 centre point
feature "SweepSrf4" sketch "Sketch4" dims "d3" = 0
workplane "Work Plane5"
sketch "Sketch5"
  geometry: C1 r 1.388 at (0, 0); 1 further point
  constraints: 1 centre point
feature "SweepSrf5" sketch "Sketch5" dims "d4" = 0
workpoint "Work Point124"
sketch "Segment6"
workpoint "Work Point125"
workpoint "Work Point126"
workpoint "Work Point127"
workplane "Work Plane6"
sketch "Sketch6"
  geometry: C1 r 1.388 at (0, 0); 1 further point
  constraints: 1 centre point
feature "SweepSrf6" sketch "Sketch6" dims "d5" = 0
workpoint "Work Point128"
sketch "Segment7"
workpoint "Work Point129"
workplane "Work Plane7"
sketch "Sketch7"
  geometry: C1 r 1.388 at (0, 0); 1 further point
  constraints: 1 centre point
feature "SweepSrf7" sketch "Sketch7" dims "d6" = 0
workpoint "Work Point130"
workpoint "Work Point131"
sketch "Wire1"
workpoint "Work Point132"
workpoint "Work Point133"
sketch "Wire2"
workpoint "Work Point134"
workpoint "Work Point135"
sketch "Wire3"
workpoint "Work Point136"
workpoint "Work Point137"
sketch "Wire4"
workpoint "Work Point138"
workpoint "Work Point139"
sketch "Wire5"
workpoint "Work Point140"
workpoint "Work Point141"
sketch "Wire6"
workpoint "Work Point142"
workpoint "Work Point143"
sketch "Wire7"
workpoint "Work Point144"
workpoint "Work Point145"
sketch "Wire8"
workpoint "Work Point146"
workpoint "Work Point147"
sketch "Wire9"
workpoint "Work Point148"
workpoint "Work Point149"
sketch "Wire10"
workpoint "Work Point150"
workpoint "Work Point151"
sketch "Wire11"
workpoint "Work Point152"
workpoint "Work Point153"
sketch "Wire12"
workpoint "Work Point154"
workpoint "Work Point155"
sketch "Wire13"
workpoint "Work Point156"
workpoint "Work Point157"
sketch "Wire14"
workpoint "Work Point158"
workpoint "Work Point159"
sketch "Wire15"
workpoint "Work Point160"
workpoint "Work Point161"
sketch "Wire16"
workpoint "Work Point162"
workpoint "Work Point163"
sketch "Wire17"
workpoint "Work Point164"
workpoint "Work Point165"
sketch "Wire18"
workpoint "Work Point166"
workpoint "Work Point167"
sketch "Wire19"
workpoint "Work Point168"
workpoint "Work Point169"
sketch "Wire20"
workpoint "Work Point170"
workpoint "Work Point171"
sketch "Wire21"
workpoint "Work Point172"
workpoint "Work Point173"
sketch "Wire22"
workpoint "Work Point174"
workpoint "Work Point175"
sketch "Wire23"
workpoint "Work Point176"
workpoint "Work Point177"
sketch "Wire24"
workpoint "Work Point178"
workpoint "Work Point179"
sketch "Wire25"
workpoint "Work Point180"
workpoint "Work Point181"
sketch "Wire26"
workpoint "Work Point182"
workpoint "Work Point183"
sketch "Wire27"
workpoint "Work Point184"
workpoint "Work Point185"
sketch "Wire28"
workpoint "Work Point186"
workpoint "Work Point187"
sketch "Wire29"
workpoint "Work Point188"
workpoint "Work Point189"
sketch "Wire30"
workpoint "Work Point190"
workpoint "Work Point191"
sketch "Wire31"
workpoint "Work Point192"
workpoint "Work Point193"
sketch "Wire32"
workpoint "Work Point194"
workpoint "Work Point195"
sketch "Wire33"
workpoint "Work Point196"
workpoint "Work Point197"
sketch "Wire34"
workpoint "Work Point198"
workpoint "Work Point199"
sketch "Wire35"
workpoint "Work Point200"
workpoint "Work Point201"
sketch "Wire36"
workpoint "Work Point202"
workpoint "Work Point203"
sketch "Wire37"
workpoint "Work Point204"
workpoint "Work Point205"
sketch "Wire38"
workpoint "Work Point206"
workpoint "Work Point207"
sketch "Wire39"
workpoint "Work Point208"
workpoint "Work Point209"
sketch "Wire40"
workpoint "Work Point210"
workpoint "Work Point211"
sketch "Wire41"
workpoint "Work Point212"
workpoint "Work Point213"
sketch "Wire42"
workpoint "Work Point214"
workpoint "Work Point215"
sketch "Wire43"
workpoint "Work Point216"
workpoint "Work Point217"
sketch "Wire44"
workpoint "Work Point218"
workpoint "Work Point219"
workpoint "Work Point220"
workpoint "Work Point221"
workpoint "Work Point222"
workpoint "Work Point223"
workpoint "Work Point224"
workpoint "Work Point225"
workpoint "Work Point226"
workplane "Work Plane8"
sketch "Sketch8"
  geometry: C1 r 0.47 at (0, 0); 1 further point
  constraints: 1 centre point
feature "SweepSrf8" sketch "Sketch8" dims "d7" = 0
workplane "Work Plane9"
sketch "Sketch9"
  geometry: C1 r 0.47 at (0, 0); 1 further point
  constraints: 1 centre point
feature "SweepSrf9" sketch "Sketch9" dims "d8" = 0
workplane "Work Plane10"
sketch "Sketch10"
  geometry: C1 r 0.47 at (0, 0); 1 further point
  constraints: 1 centre point
feature "SweepSrf10" sketch "Sketch10" dims "d9" = 0
workplane "Work Plane11"
sketch "Sketch11"
  geometry: C1 r 0.47 at (0, 0); 1 further point
  constraints: 1 centre point
feature "SweepSrf11" sketch "Sketch11" dims "d10" = 0
workplane "Work Plane12"
sketch "Sketch12"
  geometry: C1 r 0.47 at (0, 0); 1 further point
  constraints: 1 centre point
feature "SweepSrf12" sketch "Sketch12" dims "d11" = 0
workplane "Work Plane13"
sketch "Sketch13"
  geometry: C1 r 0.47 at (0, 0); 1 further point
  constraints: 1 centre point
feature "SweepSrf13" sketch "Sketch13" dims "d12" = 0
workplane "Work Plane14"
sketch "Sketch14"
  geometry: C1 r 0.47 at (0, 0); 1 further point
  constraints: 1 centre point
feature "SweepSrf14" sketch "Sketch14" dims "d13" = 0
workplane "Work Plane15"
sketch "Sketch15"
  geometry: C1 r 0.47 at (0, 0); 1 further point
  constraints: 1 centre point
feature "SweepSrf15" sketch "Sketch15" dims "d14" = 0
workplane "Work Plane16"
sketch "Sketch16"
  geometry: C1 r 0.47 at (0, 0); 1 further point
  constraints: 1 centre point
feature "SweepSrf16" sketch "Sketch16" dims "d15" = 0
workplane "Work Plane17"
sketch "Sketch17"
  geometry: C1 r 0.47 at (0, 0); 1 further point
  constraints: 1 centre point
feature "SweepSrf17" sketch "Sketch17" dims "d16" = 0
workplane "Work Plane18"
sketch "Sketch18"
  geometry: C1 r 0.47 at (0, 0); 1 further point
  constraints: 1 centre point
feature "SweepSrf18" sketch "Sketch18" dims "d17" = 0
workplane "Work Plane19"
sketch "Sketch19"
  geometry: C1 r 0.47 at (0, 0); 1 further point
  constraints: 1 centre point
feature "SweepSrf19" sketch "Sketch19" dims "d18" = 0
workplane "Work Plane20"
sketch "Sketch20"
  geometry: C1 r 0.47 at (0, 0); 1 further point
  constraints: 1 centre point
feature "SweepSrf20" sketch "Sketch20" dims "d19" = 0
workplane "Work Plane21"
sketch "Sketch21"
  geometry: C1 r 0.47 at (0, 0); 1 further point
  constraints: 1 centre point
feature "SweepSrf21" sketch "Sketch21" dims "d20" = 0
workplane "Work Plane22"
sketch "Sketch22"
  geometry: C1 r 0.47 at (0, 0); 1 further point
  constraints: 1 centre point
feature "SweepSrf22" sketch "Sketch22" dims "d21" = 0
workplane "Work Plane23"
sketch "Sketch23"
  geometry: C1 r 0.47 at (0, 0); 1 further point
  constraints: 1 centre point
feature "SweepSrf23" sketch "Sketch23" dims "d22" = 0
workplane "Work Plane24"
sketch "Sketch24"
  geometry: C1 r 0.47 at (0, 0); 1 further point
  constraints: 1 centre point
feature "SweepSrf24" sketch "Sketch24" dims "d23" = 0
workplane "Work Plane25"
sketch "Sketch25"
  geometry: C1 r 0.47 at (0, 0); 1 further point
  constraints: 1 centre point
feature "SweepSrf25" sketch "Sketch25" dims "d24" = 0
workplane "Work Plane26"
sketch "Sketch26"
  geometry: C1 r 0.47 at (0, 0); 1 further point
  constraints: 1 centre point
feature "SweepSrf26" sketch "Sketch26" dims "d25" = 0
workplane "Work Plane27"
sketch "Sketch27"
  geometry: C1 r 0.47 at (0, 0); 1 further point
  constraints: 1 centre point
feature "SweepSrf27" sketch "Sketch27" dims "d26" = 0
workplane "Work Plane28"
sketch "Sketch28"
  geometry: C1 r 0.47 at (0, 0); 1 further point
  constraints: 1 centre point
feature "SweepSrf28" sketch "Sketch28" dims "d27" = 0
workplane "Work Plane29"
sketch "Sketch29"
  geometry: C1 r 0.47 at (0, 0); 1 further point
  constraints: 1 centre point
feature "SweepSrf29" sketch "Sketch29" dims "d28" = 0
workplane "Work Plane30"
sketch "Sketch30"
  geometry: C1 r 0.47 at (0, 0); 1 further point
  constraints: 1 centre point
feature "SweepSrf30" sketch "Sketch30" dims "d29" = 0
workplane "Work Plane31"
sketch "Sketch31"
  geometry: C1 r 0.47 at (0, 0); 1 further point
  constraints: 1 centre point
feature "SweepSrf31" sketch "Sketch31" dims "d30" = 0
workplane "Work Plane32"
sketch "Sketch32"
  geometry: C1 r 0.47 at (0, 0); 1 further point
  constraints: 1 centre point
feature "SweepSrf32" sketch "Sketch32" dims "d31" = 0
workplane "Work Plane33"
sketch "Sketch33"
  geometry: C1 r 0.47 at (0, 0); 1 further point
  constraints: 1 centre point
feature "SweepSrf33" sketch "Sketch33" dims "d32" = 0
workplane "Work Plane34"
sketch "Sketch34"
  geometry: C1 r 0.47 at (0, 0); 1 further point
  constraints: 1 centre point
feature "SweepSrf34" sketch "Sketch34" dims "d33" = 0
workplane "Work Plane35"
sketch "Sketch35"
  geometry: C1 r 0.47 at (0, 0); 1 further point
  constraints: 1 centre point
feature "SweepSrf35" sketch "Sketch35" dims "d34" = 0
workplane "Work Plane36"
sketch "Sketch36"
  geometry: C1 r 0.47 at (0, 0); 1 further point
  constraints: 1 centre point
feature "SweepSrf36" sketch "Sketch36" dims "d35" = 0
workplane "Work Plane37"
sketch "Sketch37"
  geometry: C1 r 0.47 at (0, 0); 1 further point
  constraints: 1 centre point
feature "SweepSrf37" sketch "Sketch37" dims "d36" = 0
workplane "Work Plane38"
sketch "Sketch38"
  geometry: C1 r 0.47 at (0, 0); 1 further point
  constraints: 1 centre point
feature "SweepSrf38" sketch "Sketch38" dims "d37" = 0
workplane "Work Plane39"
sketch "Sketch39"
  geometry: C1 r 0.47 at (0, 0); 1 further point
  constraints: 1 centre point
feature "SweepSrf39" sketch "Sketch39" dims "d38" = 0
workplane "Work Plane40"
sketch "Sketch40"
  geometry: C1 r 0.47 at (0, 0); 1 further point
  constraints: 1 centre point
feature "SweepSrf40" sketch "Sketch40" dims "d39" = 0
workplane "Work Plane41"
sketch "Sketch41"
  geometry: C1 r 0.47 at (0, 0); 1 further point
  constraints: 1 centre point
feature "SweepSrf41" sketch "Sketch41" dims "d40" = 0
workplane "Work Plane42"
sketch "Sketch42"
  geometry: C1 r 0.47 at (0, 0); 1 further point
  constraints: 1 centre point
feature "SweepSrf42" sketch "Sketch42" dims "d41" = 0
workplane "Work Plane43"
sketch "Sketch43"
  geometry: C1 r 0.47 at (0, 0); 1 further point
  constraints: 1 centre point
feature "SweepSrf43" sketch "Sketch43" dims "d42" = 0
workplane "Work Plane44"
sketch "Sketch44"
  geometry: C1 r 0.47 at (0, 0); 1 further point
  constraints: 1 centre point
feature "SweepSrf44" sketch "Sketch44" dims "d43" = 0
workplane "Work Plane45"
sketch "Sketch45"
  geometry: C1 r 0.47 at (0, 0); 1 further point
  constraints: 1 centre point
feature "SweepSrf45" sketch "Sketch45" dims "d44" = 0
workplane "Work Plane46"
sketch "Sketch46"
  geometry: C1 r 0.47 at (0, 0); 1 further point
  constraints: 1 centre point
feature "SweepSrf46" sketch "Sketch46" dims "d45" = 0
workplane "Work Plane47"
sketch "Sketch47"
  geometry: C1 r 0.47 at (0, 0); 1 further point
  constraints: 1 centre point
feature "SweepSrf47" sketch "Sketch47" dims "d46" = 0
workplane "Work Plane48"
sketch "Sketch48"
  geometry: C1 r 0.61 at (0, 0); 1 further point
  constraints: 1 centre point
feature "SweepSrf48" sketch "Sketch48" dims "d47" = 0
workplane "Work Plane49"
sketch "Sketch49"
  geometry: C1 r 0.61 at (0, 0); 1 further point
  constraints: 1 centre point
feature "SweepSrf49" sketch "Sketch49" dims "d48" = 0
workplane "Work Plane50"
sketch "Sketch50"
  geometry: C1 r 0.61 at (0, 0); 1 further point
  constraints: 1 centre point
feature "SweepSrf50" sketch "Sketch50" dims "d49" = 0
workplane "Work Plane51"
sketch "Sketch51"
  geometry: C1 r 0.61 at (0, 0); 1 further point
  constraints: 1 centre point
feature "SweepSrf51" sketch "Sketch51" dims "d50" = 0
workplane "Work Plane52"
sketch "Sketch52"
  geometry: C1 r 0.61 at (0, 0); 1 further point
  constraints: 1 centre point
feature "SweepSrf52" sketch "Sketch52" dims "d51" = 0
workplane "Work Plane53"
sketch "Sketch53"
  geometry: C1 r 0.61 at (0, 0); 1 further point
  constraints: 1 centre point
feature "SweepSrf53" sketch "Sketch53" dims "d52" = 0
workplane "Work Plane54"
sketch "Sketch54"
  geometry: C1 r 0.61 at (0, 0); 1 further point
  constraints: 1 centre point
feature "SweepSrf54" sketch "Sketch54" dims "d53" = 0
workplane "Work Plane55"
sketch "Sketch55"
  geometry: C1 r 0.61 at (0, 0); 1 further point
  constraints: 1 centre point
feature "SweepSrf55" sketch "Sketch55" dims "d54" = 0
workplane "Work Plane56"
sketch "Sketch56"
  geometry: C1 r 0.61 at (0, 0); 1 further point
  constraints: 1 centre point
feature "SweepSrf56" sketch "Sketch56" dims "d55" = 0
workplane "Work Plane57"
sketch "Sketch57"
  geometry: C1 r 0.61 at (0, 0); 1 further point
  constraints: 1 centre point
feature "SweepSrf57" sketch "Sketch57" dims "d56" = 0
workplane "Work Plane58"
sketch "Sketch58"
  geometry: C1 r 0.61 at (0, 0); 1 further point
  constraints: 1 centre point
